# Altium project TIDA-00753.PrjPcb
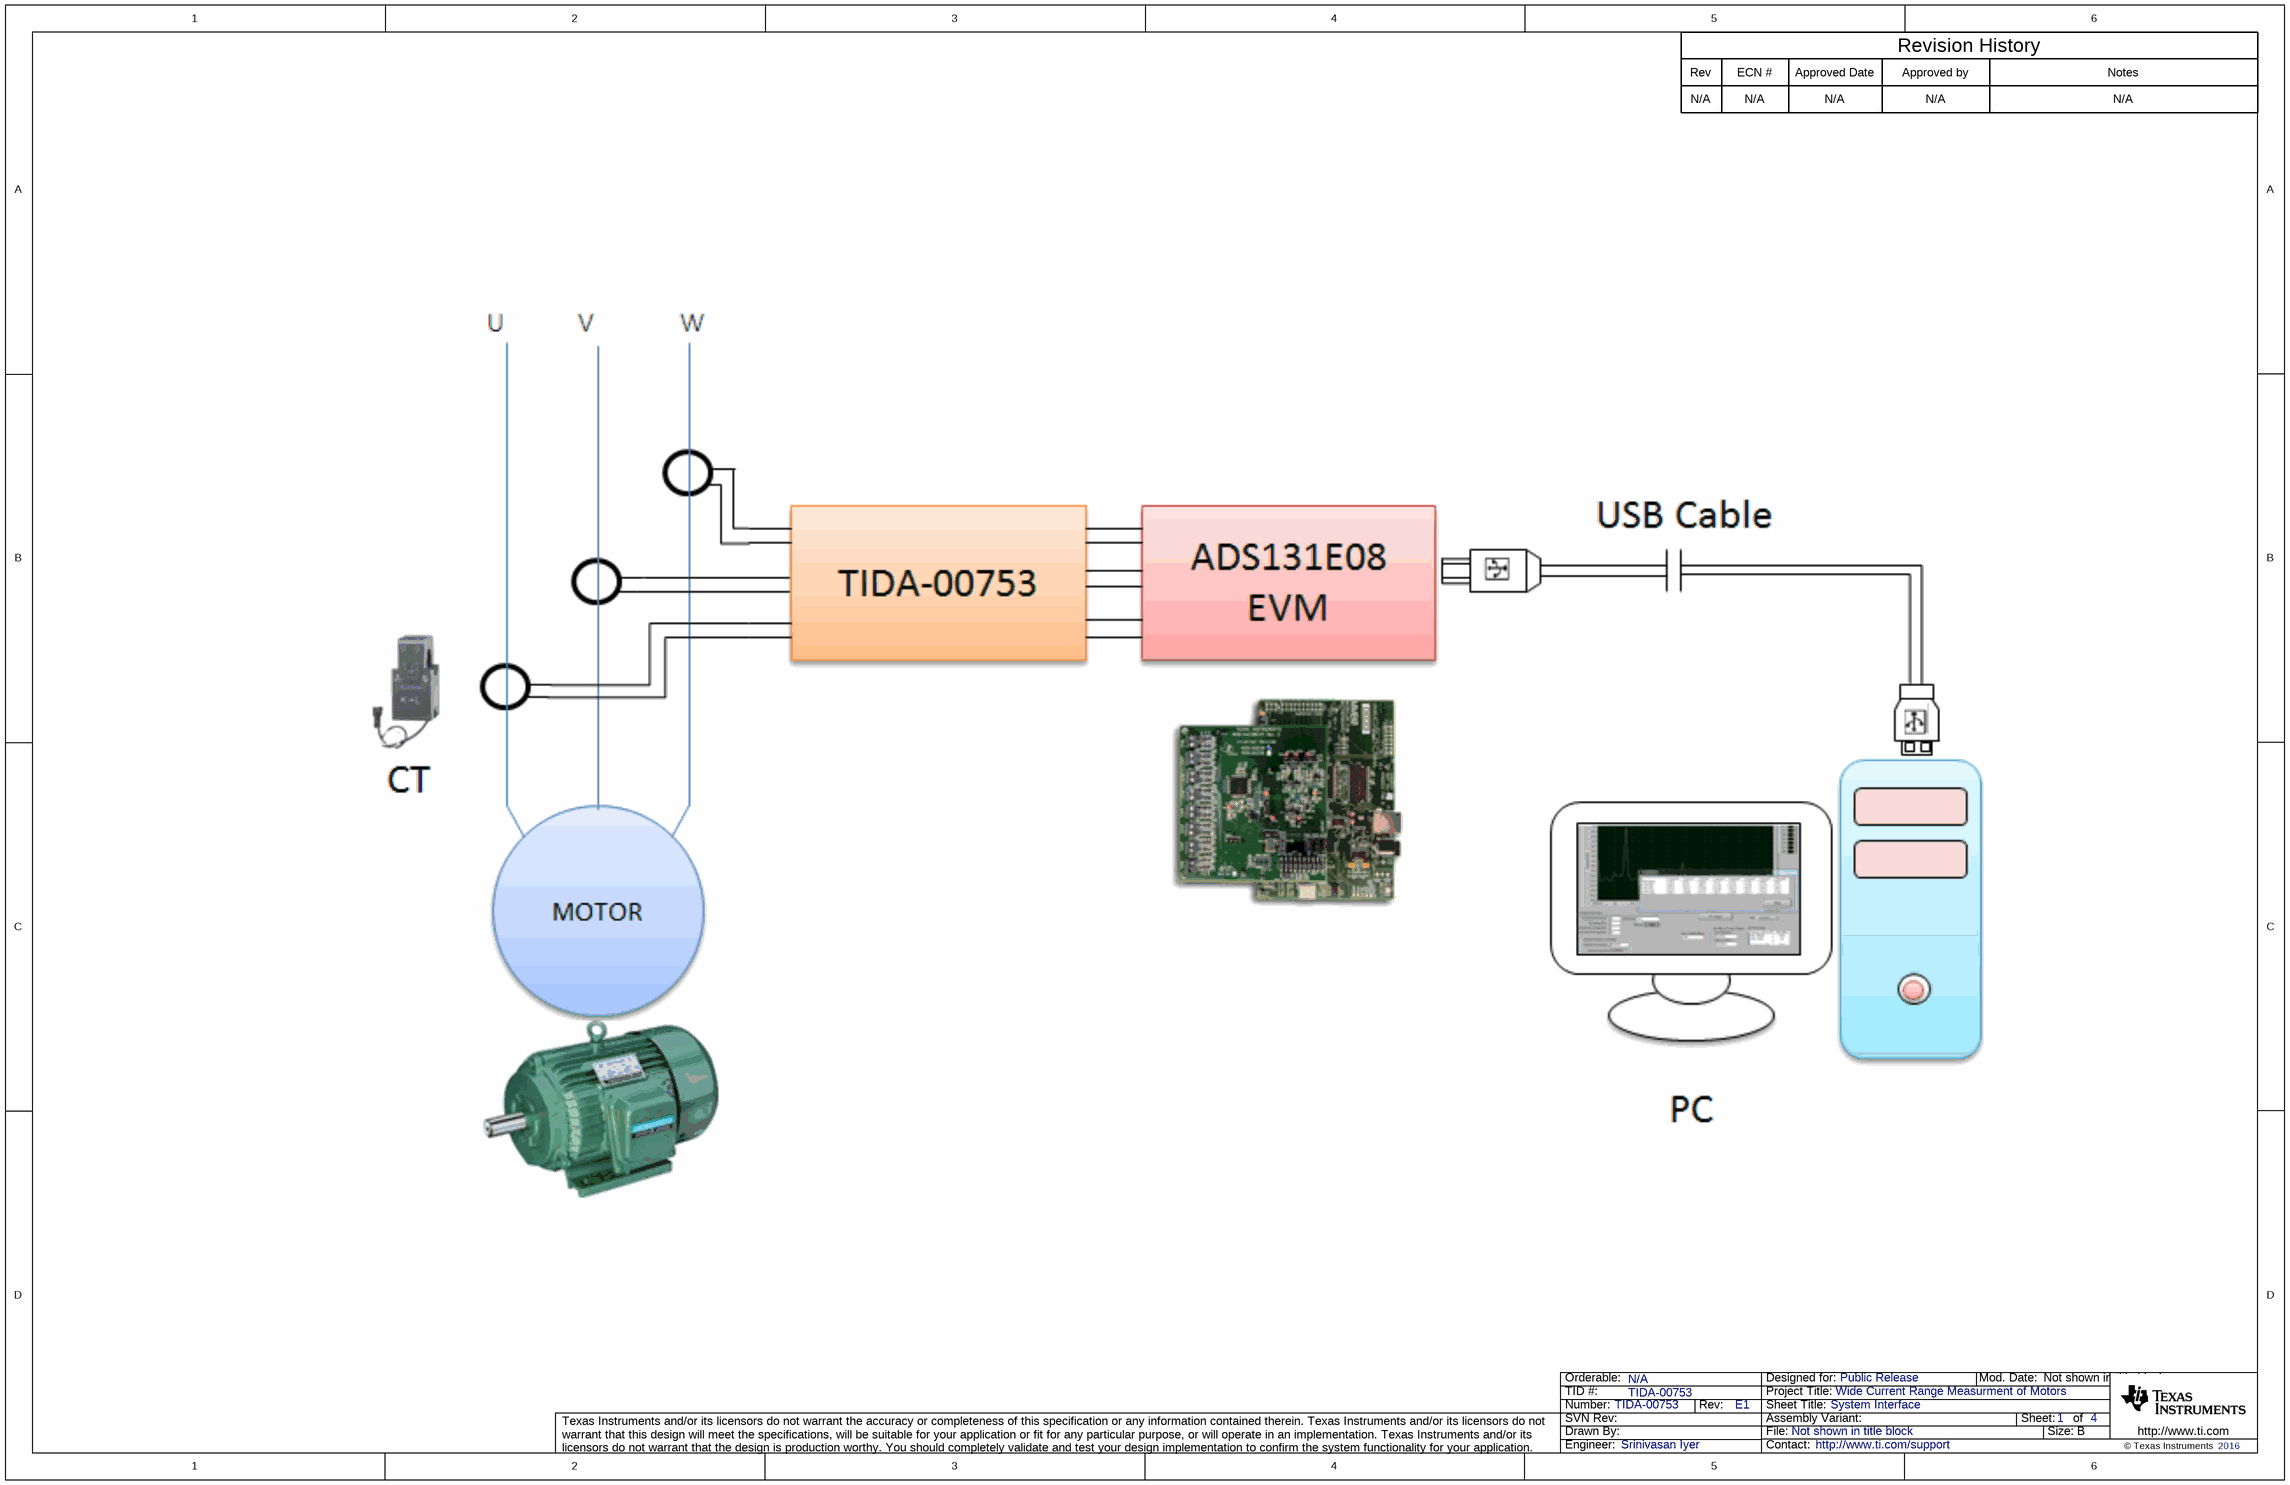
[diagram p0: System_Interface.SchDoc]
TID: TIDA-00753; TechSupport: http://www.ti.com/support; SCH_Rev: E1; PRJ_Title: Wide Current Range Measurment of Motors; PRJ_Number: TIDA-00753; PRJ_Engineer: Srinivasan Iyer; PRJ_Customer: Public Release; PCB_Rev: E1; PCB_Layout: Avinash; EVM_Orderable: N/A; CopyrightYear: 2016
4 sheets, 93 parts. Net scope: global (net labels, ports and power ports of the same name join across sheets).
Board file: TIDA-00753.PcbDoc
Sheets:
  System_Interface.SchDoc
  TIDA-00753_Block Diagram.SchDoc
  Amplifier.SchDoc
  TID_Hardware.SchDoc

## Sheet System_Interface.SchDoc: System Interface
size 431 x 279 mm; Date: Not shown in title block; ApprovedBy: Not shown in title block; CheckedBy: Not shown in title block; Author: Not shown in title block; CompanyName: Not shown in title block; Engineer: Not shown in title block; Organization: Not shown in title block; Address1: Not shown in title block; Address2: Not shown in title block; Address3: Not shown in title block; Address4: Not shown in title block; DocumentNumber: 1; Revision: Use project parameter SCH_Rev; SheetNumber: 1; SheetTotal: 4; PageSetup: Record=PageOptions¦CenterHorizontal=True¦CenterVertical=True¦PrintScale=1.00¦XCorrection=1.00¦YCorrection=1.00¦PrintKind=0¦BorderSize=5000000¦LeftOffset=0¦BottomOffset=0¦Orientation=2¦PaperLength=1000¦PaperWidth=1000¦Scale=100¦PaperSource=15¦PrintQuality=600¦MediaType=1¦DitherType=10¦PaperKind=Letter¦PrintScaleMode=1

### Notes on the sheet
- Rev
- N/A
- ECN #
- Approved Date
- Approved by
- Revision History
- Notes

## Sheet TIDA-00753_Block Diagram.SchDoc: TIDA-00753 Block Diagram
size 431 x 279 mm; Date: Not shown in title block; ApprovedBy: Not shown in title block; CheckedBy: Not shown in title block; Author: Not shown in title block; CompanyName: Not shown in title block; Engineer: Not shown in title block; Organization: Not shown in title block; Address1: Not shown in title block; Address2: Not shown in title block; Address3: Not shown in title block; Address4: Not shown in title block; DocumentNumber: 1; Revision: Use project parameter SCH_Rev; SheetNumber: 2; SheetTotal: 4; PageSetup: Record=PageOptions¦CenterHorizontal=True¦CenterVertical=True¦PrintScale=1.00¦XCorrection=1.00¦YCorrection=1.00¦PrintKind=0¦BorderSize=5000000¦LeftOffset=0¦BottomOffset=0¦Orientation=2¦PaperLength=1000¦PaperWidth=1000¦Scale=100¦PaperSource=15¦PrintQuality=600¦MediaType=1¦DitherType=10¦PaperKind=Letter¦PrintScaleMode=1
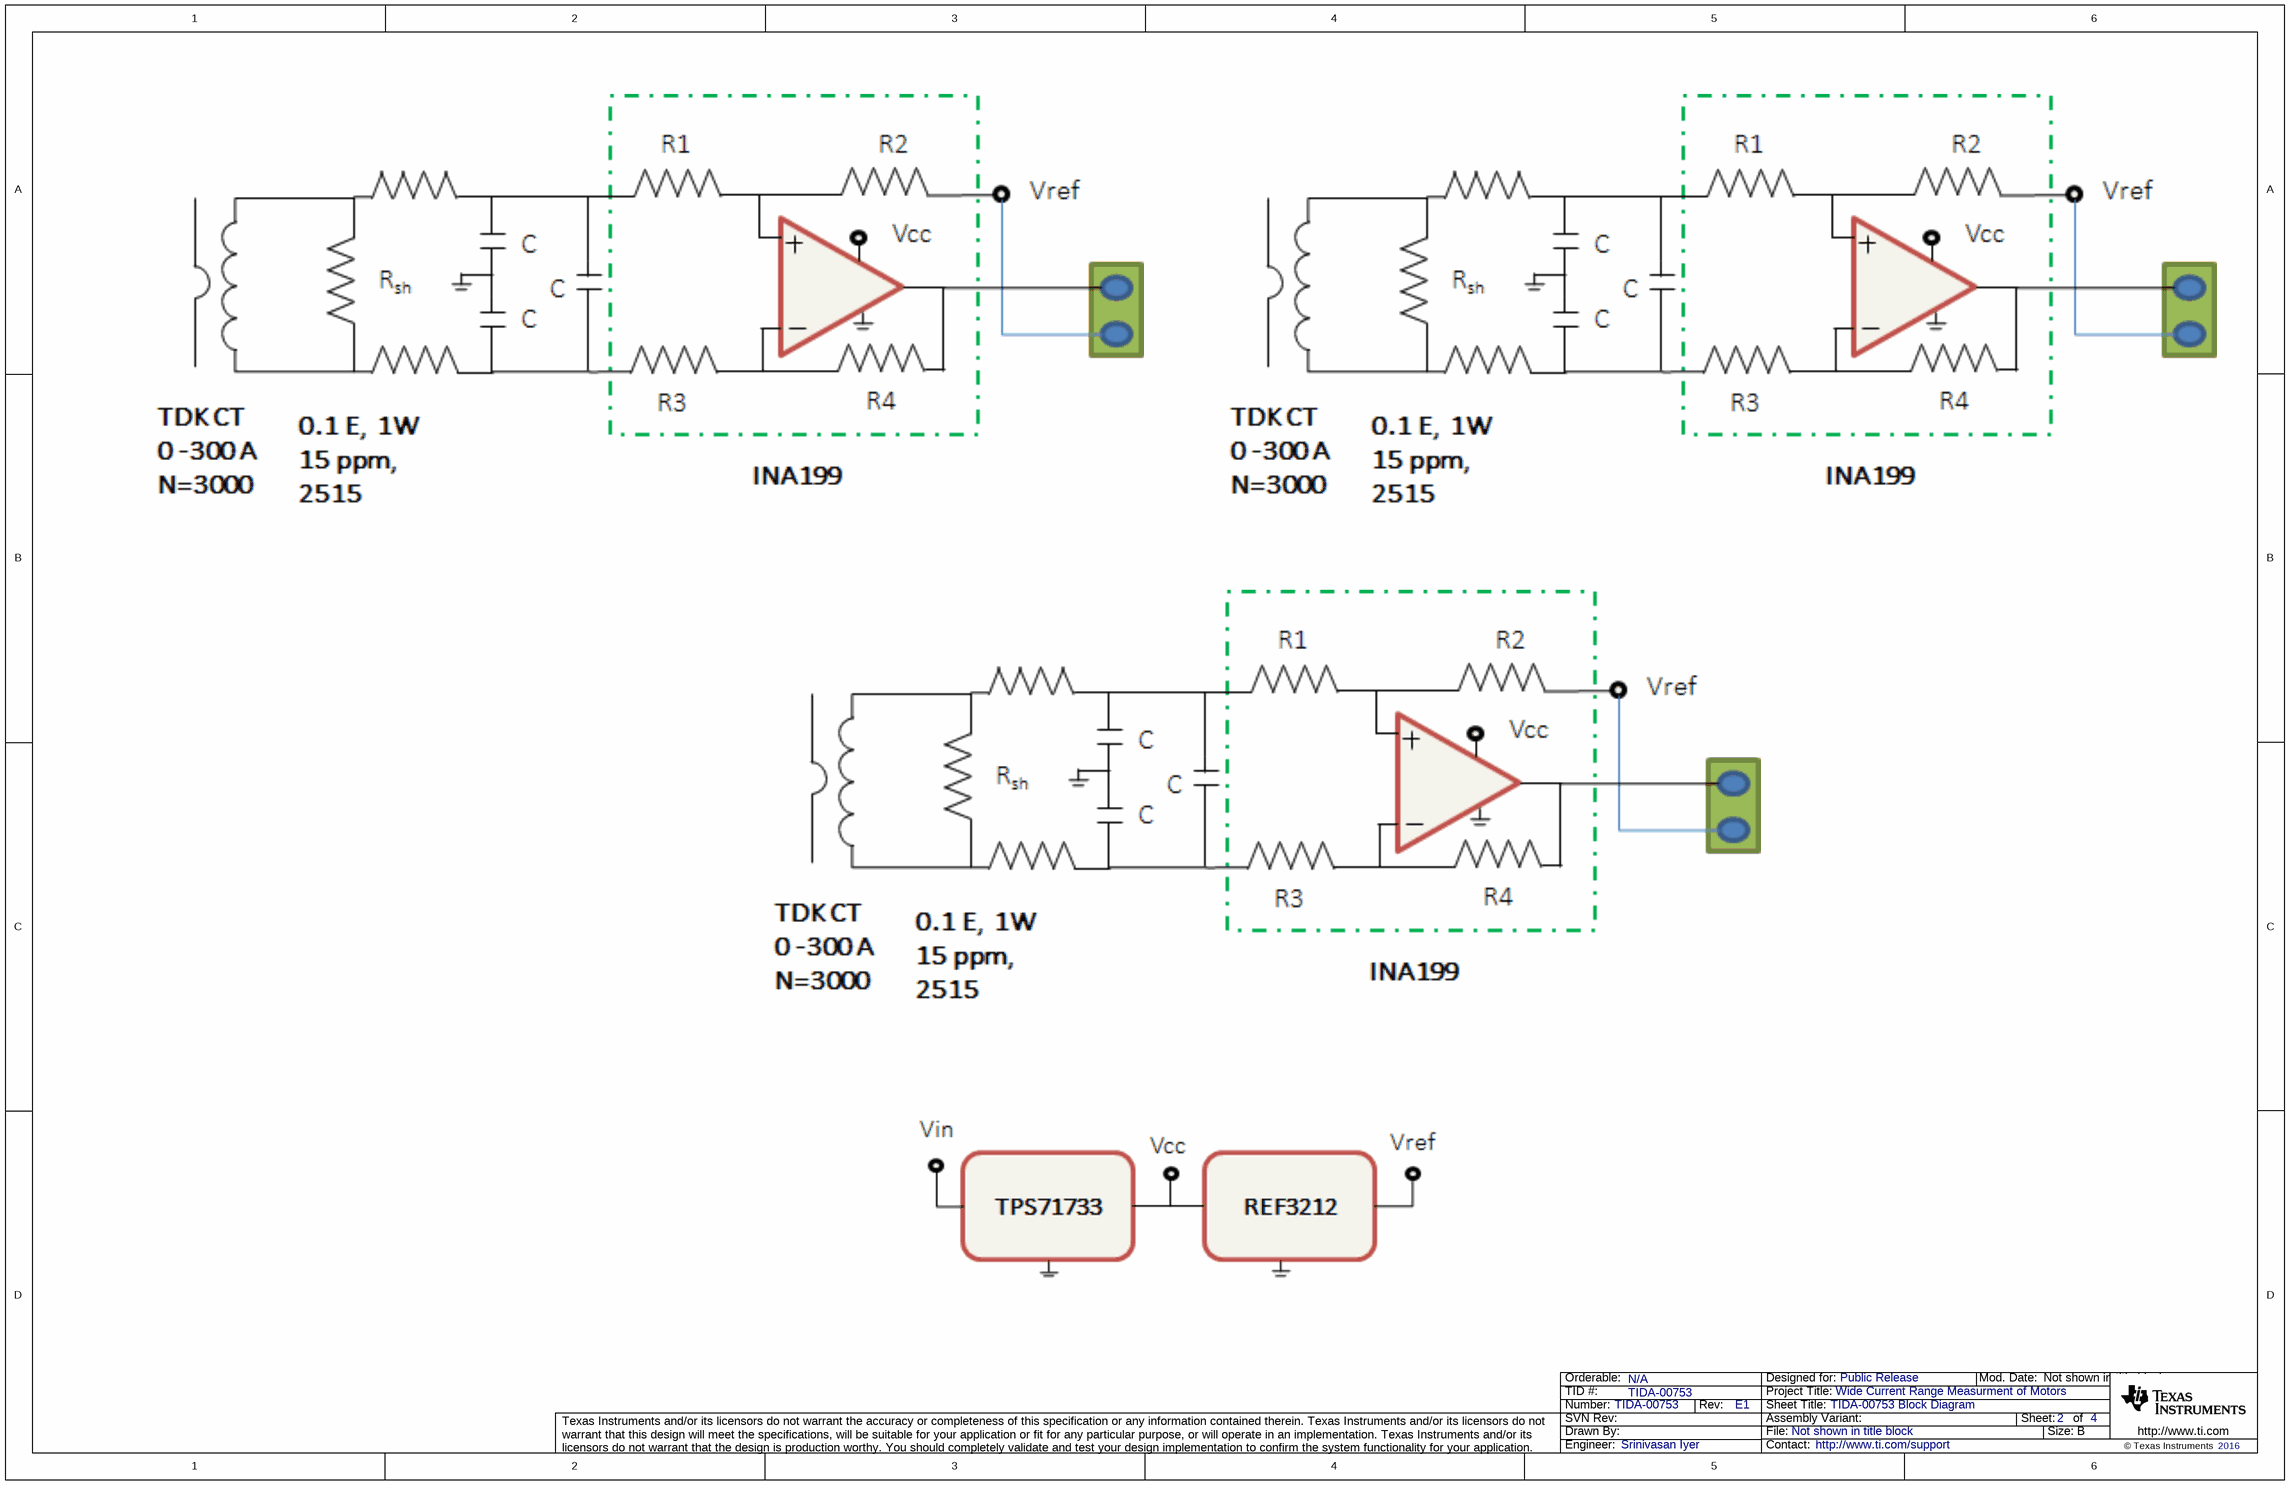
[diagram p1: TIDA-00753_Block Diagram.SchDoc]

## Sheet Amplifier.SchDoc: CT Amplifier
size 431 x 279 mm; Date: Not shown in title block; ApprovedBy: Not shown in title block; CheckedBy: Not shown in title block; Author: Not shown in title block; CompanyName: Not shown in title block; DrawnBy: Srinivasan Iyer; Engineer: Srinivasan Iyer; Organization: Not shown in title block; Address1: Not shown in title block; Address2: Not shown in title block; Address3: Not shown in title block; Address4: Not shown in title block; DocumentNumber: 1; Revision: Use project parameter SCH_Rev; SheetNumber: 3; SheetTotal: 4; PageSetup: Record=PageOptions¦CenterHorizontal=True¦CenterVertical=True¦PrintScale=0.64¦XCorrection=1.00¦YCorrection=1.00¦PrintKind=0¦BorderSize=5000000¦LeftOffset=0¦BottomOffset=0¦Orientation=2¦PaperLength=1000¦PaperWidth=1000¦Scale=100¦PaperSource=15¦PrintQuality=600¦MediaType=1¦DitherType=10¦PrintScaleMode=1¦PaperKind=Letter
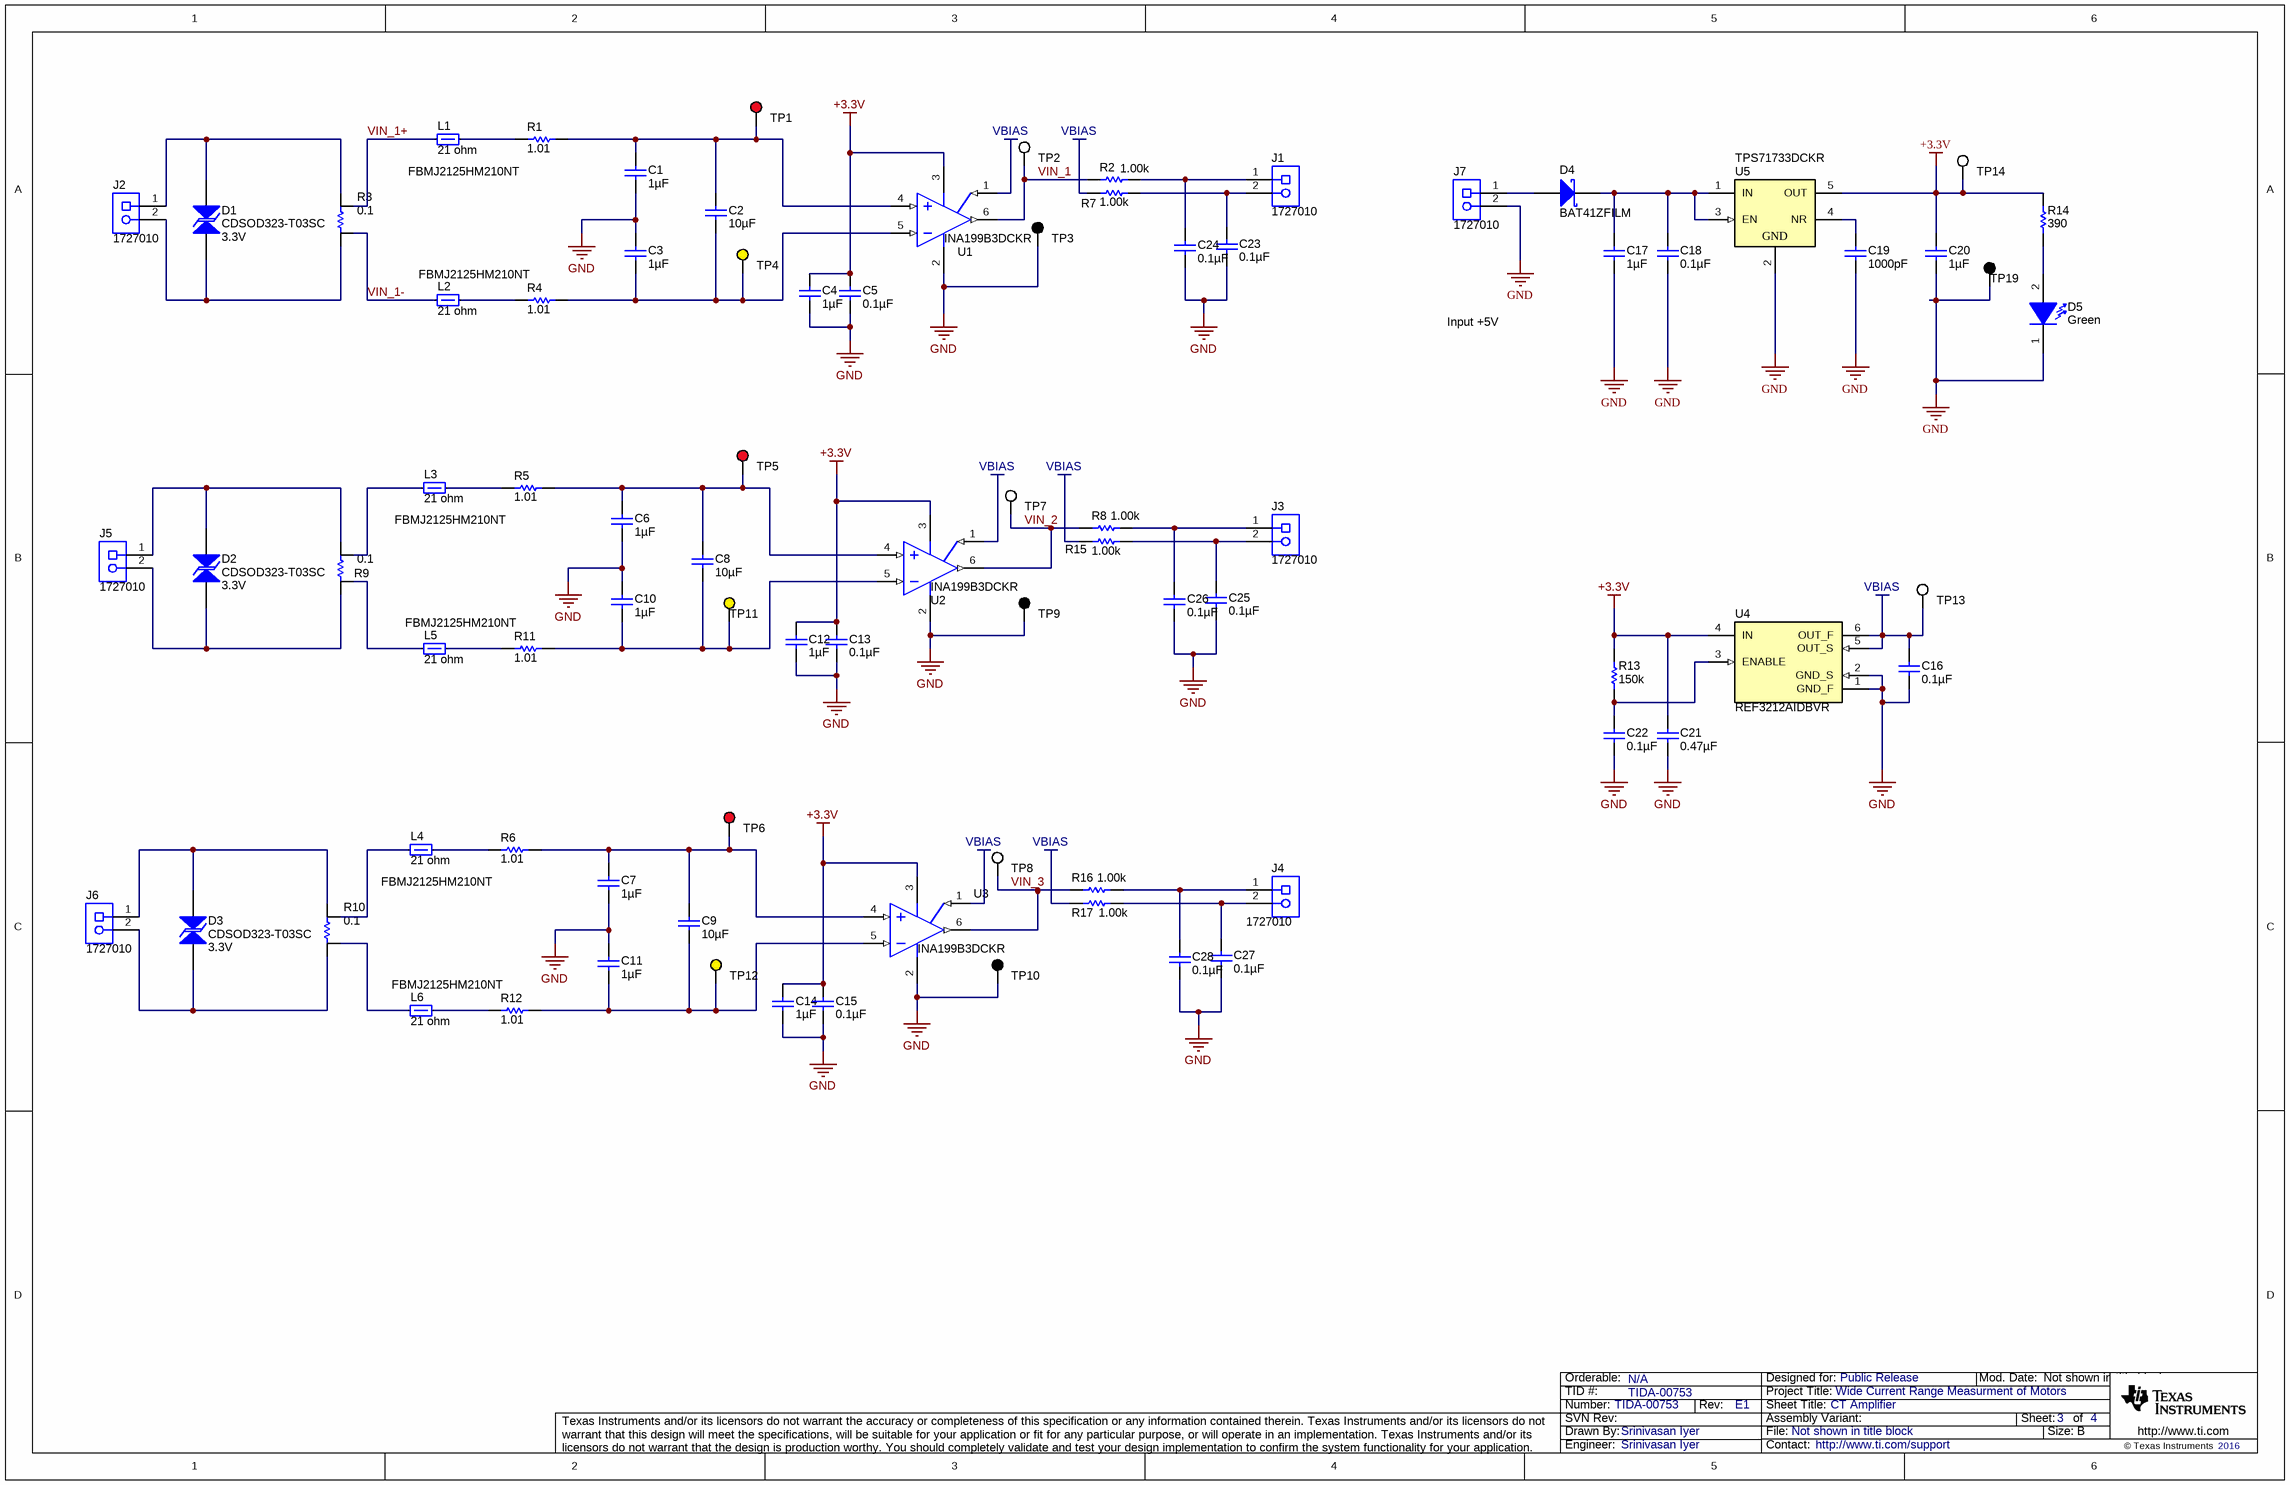
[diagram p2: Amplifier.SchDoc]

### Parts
C1  ValueDisplayed: 1µF  [0603]  (hidden comment: C1608X5R1C105K)
C2  ValueDisplayed: 10µF  [0603]  (hidden comment: GRM188R60J106ME47D)
C3  ValueDisplayed: 1µF  [0603]  (hidden comment: C1608X5R1C105K)
C4  ValueDisplayed: 1µF  [0603]  (hidden comment: C1608X5R1C105K)
C5  ValueDisplayed: 0.1µF  [0603]  (hidden comment: CGA3E2X8R1E104K080AA)
C6  ValueDisplayed: 1µF  [0603]  (hidden comment: C1608X5R1C105K)
C7  ValueDisplayed: 1µF  [0603]  (hidden comment: C1608X5R1C105K)
C8  ValueDisplayed: 10µF  [0603]  (hidden comment: GRM188R60J106ME47D)
C9  ValueDisplayed: 10µF  [0603]  (hidden comment: GRM188R60J106ME47D)
C10  ValueDisplayed: 1µF  [0603]  (hidden comment: C1608X5R1C105K)
C11  ValueDisplayed: 1µF  [0603]  (hidden comment: C1608X5R1C105K)
C12  ValueDisplayed: 1µF  [0603]  (hidden comment: C1608X5R1C105K)
C13  ValueDisplayed: 0.1µF  [0603]  (hidden comment: CGA3E2X8R1E104K080AA)
C14  ValueDisplayed: 1µF  [0603]  (hidden comment: C1608X5R1C105K)
C15  ValueDisplayed: 0.1µF  [0603]  (hidden comment: CGA3E2X8R1E104K080AA)
C16  ValueDisplayed: 0.1µF  [0603]  (hidden comment: CGA3E2X8R1E104K080AA)
C17  ValueDisplayed: 1µF  [0603]  (hidden comment: C1608X5R1C105K)
C18  ValueDisplayed: 0.1µF  [0603]  (hidden comment: CGA3E2X8R1E104K080AA)
C19  ValueDisplayed: 1000pF  [0603]  (hidden comment: C0603X102K5RACTU)
C20  ValueDisplayed: 1µF  [0603]  (hidden comment: C1608X5R1C105K)
C21  ValueDisplayed: 0.47µF  [0603]  (hidden comment: C0603C474K4RACTU)
C22  ValueDisplayed: 0.1µF  [0603]  (hidden comment: CGA3E2X8R1E104K080AA)
C23  ValueDisplayed: 0.1µF  [0603]  (hidden comment: CGA3E2X8R1E104K080AA)
C24  ValueDisplayed: 0.1µF  [0603]  (hidden comment: CGA3E2X8R1E104K080AA)
C25  ValueDisplayed: 0.1µF  [0603]  (hidden comment: CGA3E2X8R1E104K080AA)
C26  ValueDisplayed: 0.1µF  [0603]  (hidden comment: CGA3E2X8R1E104K080AA)
C27  ValueDisplayed: 0.1µF  [0603]  (hidden comment: CGA3E2X8R1E104K080AA)
C28  ValueDisplayed: 0.1µF  [0603]  (hidden comment: CGA3E2X8R1E104K080AA)
D1  CDSOD323-T03SC  value 3.3V  [SOD-323-Bi]
D2  CDSOD323-T03SC  value 3.3V  [SOD-323-Bi]
D3  CDSOD323-T03SC  value 3.3V  [SOD-323-Bi]
D4  BAT41ZFILM  [SOD-123]
D5  value Green  [WL-SMCW_GREEN]  (hidden comment: 150060GS75000)
J1  1727010  [PhoenixConact_1727010]
J2  1727010  [PhoenixConact_1727010]
J3  1727010  [PhoenixConact_1727010]
J4  1727010  [PhoenixConact_1727010]
J5  1727010  [PhoenixConact_1727010]
J6  1727010  [PhoenixConact_1727010]
J7  1727010  [PhoenixConact_1727010]
L1  value 21 ohm  [0805_HV]  (hidden comment: FBMJ2125HM210NT)
L2  value 21 ohm  [0805_HV]  (hidden comment: FBMJ2125HM210NT)
L3  value 21 ohm  [0805_HV]  (hidden comment: FBMJ2125HM210NT)
L4  value 21 ohm  [0805_HV]  (hidden comment: FBMJ2125HM210NT)
L5  value 21 ohm  [0805_HV]  (hidden comment: FBMJ2125HM210NT)
L6  value 21 ohm  [0805_HV]  (hidden comment: FBMJ2125HM210NT)
R1  ValueDisplayed: 1.01  [0603]  (hidden comment: RT0603DRE071R01L)
R2  ValueDisplayed: 1.00k  [0603]  (hidden comment: RT0603DRE071KL)
R3  ValueDisplayed: 0.1  [CSM2512_T3]  (hidden comment: Y14870R10000B9W)
R4  ValueDisplayed: 1.01  [0603]  (hidden comment: RT0603DRE071R01L)
R5  ValueDisplayed: 1.01  [0603]  (hidden comment: RT0603DRE071R01L)
R6  ValueDisplayed: 1.01  [0603]  (hidden comment: RT0603DRE071R01L)
R7  ValueDisplayed: 1.00k  [0603]  (hidden comment: RT0603DRE071KL)
R8  ValueDisplayed: 1.00k  [0603]  (hidden comment: RT0603DRE071KL)
R9  ValueDisplayed: 0.1  [CSM2512_T3]  (hidden comment: Y14870R10000B9W)
R10  ValueDisplayed: 0.1  [CSM2512_T3]  (hidden comment: Y14870R10000B9W)
R11  ValueDisplayed: 1.01  [0603]  (hidden comment: RT0603DRE071R01L)
R12  ValueDisplayed: 1.01  [0603]  (hidden comment: RT0603DRE071R01L)
R13  ValueDisplayed: 150k  [0603]  (hidden comment: CRCW0603150KFKEA)
R14  ValueDisplayed: 390  [0603]  (hidden comment: RC0603FR-07390RL)
R15  ValueDisplayed: 1.00k  [0603]  (hidden comment: RT0603DRE071KL)
R16  ValueDisplayed: 1.00k  [0603]  (hidden comment: RT0603DRE071KL)
R17  ValueDisplayed: 1.00k  [0603]  (hidden comment: RT0603DRE071KL)
TP1  5000  [Keystone5000]  (value not drawn)
TP2  5002  [Keystone5002]  (value not drawn)
TP3  5001  [Keystone5001]  (value not drawn)
TP4  5004  [Keystone5004]  (value not drawn)
TP5  5000  [Keystone5000]  (value not drawn)
TP6  5000  [Keystone5000]  (value not drawn)
TP7  5002  [Keystone5002]  (value not drawn)
TP8  5002  [Keystone5002]  (value not drawn)
TP9  5001  [Keystone5001]  (value not drawn)
TP10  5001  [Keystone5001]  (value not drawn)
TP11  5004  [Keystone5004]  (value not drawn)
TP12  5004  [Keystone5004]  (value not drawn)
TP13  5002  [Keystone5002]  (value not drawn)
TP14  5002  [Keystone5002]  (value not drawn)
TP19  5001  [Keystone5001]  (value not drawn)
U1  INA199B3DCKR  [DCK0006A_N]
U2  INA199B3DCKR  [DCK0006A_N]
U3  INA199B3DCKR  [DCK0006A_N]
U4  REF3212AIDBVR  [DBV0006A_N]
U5  TPS71733DCKR  [DCK0005A_N]

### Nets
+3.3V: C4.1 C5.1 C12.1 C13.1 C14.1 C15.1 C20.1 C21.1 R13.2 R14.2 TP14.1 U1.3(VCC) U2.3(VCC) U3.3(VCC) U4.4(IN) U5.5(OUT)
GND: C1.2 C3.1 C4.2 C5.2 C6.2 C7.2 C10.1 C11.1 C12.2 C13.2 C14.2 C15.2 C16.2 C17.2 C18.2 C19.2 C20.2 C21.2 C22.2 C23.2 C24.2 C25.2 C26.2 C27.2 C28.2 D5.1(K) J7.2 TP3.1 TP9.1 TP10.1 TP19.1 U1.2(GND) U2.2(GND) U3.2(GND) U4.1(GND_F) U4.2(GND_S) U5.2(GND)
VBIAS: C16.1 R7.1 R15.1 R17.1 TP13.1 U1.1(REF) U2.1(REF) U3.1(REF) U4.5(OUT_S) U4.6(OUT_F)
VIN_1: R2.1 TP2.1 U1.6(OUT)
VIN_1+: L1.1 R3.3
VIN_1-: L2.1 R3.4
VIN_2: R8.1 TP7.1 U2.6(OUT)
VIN_3: R16.1 TP8.1 U3.6(OUT)
NetC1_1: C1.1 C2.1 R1.2 TP1.1 U1.4(IN+)
NetC2_2: C2.2 C3.2 R4.2 TP4.1 U1.5(IN-)
NetC6_1: C6.1 C8.1 R5.2 TP5.1 U2.4(IN+)
NetC7_1: C7.1 C9.1 R6.2 TP6.1 U3.4(IN+)
NetC8_2: C8.2 C10.2 R11.2 TP11.1 U2.5(IN-)
NetC9_2: C9.2 C11.2 R12.2 TP12.1 U3.5(IN-)
NetC17_1: C17.1 C18.1 D4.1(K) U5.1(IN) U5.3(EN)
NetC19_1: C19.1 U5.4(NR)
NetC22_1: C22.1 R13.1 U4.3(ENABLE)
NetC23_1: C23.1 J1.2 R7.2
NetC24_1: C24.1 J1.1 R2.2
NetC25_1: C25.1 J3.2 R15.2
NetC26_1: C26.1 J3.1 R8.2
NetC27_1: C27.1 J4.2 R17.2
NetC28_1: C28.1 J4.1 R16.2
NetD1_1: D1.1 J2.2 R3.2
NetD1_2: D1.2 J2.1 R3.1
NetD2_1: D2.1 J5.2 R9.2
NetD2_2: D2.2 J5.1 R9.1
NetD3_1: D3.1 J6.2 R10.2
NetD3_2: D3.2 J6.1 R10.1
NetD4_2: D4.2(A) J7.1
NetD5_2: D5.2(A) R14.1
NetL1_2: L1.2 R1.1
NetL2_2: L2.2 R4.1
NetL3_1: L3.1 R9.3
NetL3_2: L3.2 R5.1
NetL4_1: L4.1 R10.3
NetL4_2: L4.2 R6.1
NetL5_1: L5.1 R9.4
NetL5_2: L5.2 R11.1
NetL6_1: L6.1 R10.4
NetL6_2: L6.2 R12.1

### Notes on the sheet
- Input +5V

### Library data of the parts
C1 C3 C4 C6 C7 C10-C12 C14 C17 C20 = C1608X5R1C105K: CAP, CERM, 1 µF, 16 V, +/- 10%, X5R, 0603; Manufacturer: TDK; Polarized: N; CompType: Capacitor; Value: 1uF; U/M: EA; Cap_F: 0.000001; Tolerance_%: 10; ESR_ohm: 0.0057; Value1: 0.0057 ohm; VDC_V: 16; Value2: 16V; TaMin_C: -55; TaMax_C: 85; AEC Category: Q200
C2 C8 C9 = GRM188R60J106ME47D: CAP, CERM, 10 µF, 6.3 V, +/- 20%, X5R, 0603; Manufacturer: MuRata; Polarized: N; CompType: Capacitor; Value: 10uF; U/M: EA; Cap_F: 0.00001; Tolerance_%: 20; ESR_ohm: 0.009; Value1: 0.009 ohm; VDC_V: 6.3; Value2: 6.3V; IRMS_A: 2.74; TaMin_C: -55; TaMax_C: 125; AEC Category: Q200
C5 C13 C15 C16 C18 C22-C28 = CGA3E2X8R1E104K080AA: CAP, CERM, 0.1 µF, 25 V, +/- 10%, X8R, AEC-Q200 Grade 0, 0603; Manufacturer: TDK; Polarized: N; CompType: Capacitor; Value: 0.1uF; U/M: EA; Cap_F: 0.0000001; Tolerance_%: 10; Value1: Unknown; VDC_V: 25; Value2: 25V; TaMin_C: -55; TaMax_C: 150; AEC Category: Q200; AEC Qualified: Y; AEC Grade: 0
C19 = C0603X102K5RACTU: CAP, CERM, 1000 pF, 50 V, +/- 10%, X7R, 0603; Manufacturer: Kemet; Polarized: N; CompType: Capacitor; Value: 1000pF; U/M: EA; Cap_F: 0.000000001; Tolerance_%: 10; Value1: Unknown; VDC_V: 50; Value2: 50V; TaMin_C: -55; TaMax_C: 125; AEC Category: Q200
C21 = C0603C474K4RACTU: CAP, CERM, 0.47 µF, 16 V, +/- 10%, X7R, 0603; Manufacturer: Kemet; Polarized: N; CompType: Capacitor; Value: 0.47uF; U/M: EA; Cap_F: 0.00000047; Tolerance_%: 10; Value1: Unknown; VDC_V: 16; Value2: 16V; TaMin_C: -55; TaMax_C: 125; AEC Category: Q200
D1-D3 = CDSOD323-T03SC: Diode, TVS, Bi, 3.3 V, 400 W, SOD323, 2-Leads, Body 1.9x1.45mm, No Polarity Mark; Manufacturer: Bourns; U/M: EA; Power_W: 400; Vr_V: 3.3; Value1: 400W; AEC Category: Q101; AEC Qualified: N
D4 = BAT41ZFILM: Diode, Schottky, 100 V, 0.2 A, SOD-123; Manufacturer: STMicroelectronics; U/M: EA; Vf_V: 1; Value: 100V; Value1: 0.2A; Value2: 1V; Io_A: 0.2; Vr_V: 100; TJmax_C: 150; AEC Category: Q101
D5 = 150060GS75000: LED, Green, SMD; Manufacturer: Wurth Elektronik; Type: InGaN; Vf_V: 3.2; Value2: 3.2V; Io_A: 0.02; Tjmax_C: 85; Value1: W; Angle: 140; U/M: EA
J1-J7 = 1727010: Conn Term Block, 2POS, 3.81mm, TH; Manufacturer: Phoenix Contact; SymbolCreator: a0412235; CompType: Terminal Block; U/M: EA; Value: 2x1
L1-L6 = FBMJ2125HM210NT: Ferrite Bead, 21 ohm @ 100 MHz, 6 A, 0805; Manufacturer: Taiyo Yuden; Imax_A: 6; DCR_ohm: 0.004; Value1: 0.004 ohm; Value2: 6A; ZTyp@100MHz_Ohm: 21
R1 R4-R6 R11 R12 = RT0603DRE071R01L: RES, 1.01, 0.5%, 0.1 W, 0603; Manufacturer: Yageo America; CompType: Resistor; Value: 1.01; Value_Code: 1R01; Tolerance_%: 0.5; Power_W: 0.1; Value2: 0.1W; VDC_V: 75; TempCo: 50 ppm/C; EIA_Code: E192; U/M: EA; AEC Category: Q200
R2 R7 R8 R15-R17 = RT0603DRE071KL: RES, 1.00 k, 0.5%, 0.1 W, 0603; Manufacturer: Yageo America; CompType: Resistor; Value: 1.00k; Res_ohm: 1000; Value_Code: 1k00; Tolerance_%: 0.5; Power_W: 0.1; Value2: 0.1W; VDC_V: 75; TempCo: 50 ppm/C; EIA_Code: E192; U/M: EA; AEC Category: Q200
R3 R9 R10 = Y14870R10000B9W: RES, 0.1, 0.1%, 1 W, 6.35x3.175mm; Manufacturer: Vishay Foil Resistors; CompType: Resistor; Value: 0.1; Value_Code: R100; Power_W: 1; Value2: 1W; TempCo: 15 ppm/C; EIA_Code: E192; U/M: EA; AEC Category: Q200; AEC Qualified: N
R13 = CRCW0603150KFKEA: RES, 150 k, 1%, 0.1 W, 0603; Manufacturer: Vishay-Dale; CompType: Resistor; Value: 150k; Res_ohm: 150000; Tolerance_%: 1; Power_W: 0.1; Value2: 0.1W; VDC_V: 75; TempCo: 100 ppm/C; EIA_Code: E96; U/M: EA; AEC Category: Q200
R14 = RC0603FR-07390RL: RES, 390, 1%, 0.1 W, 0603; Manufacturer: Yageo America; CompType: Resistor; Value: 390; Value_Code: 390R; Tolerance_%: 1; Power_W: 0.1; Value2: 0.1W; VDC_V: 150; TempCo: 200 ppm/C; U/M: EA; AEC Category: Q200
TP1 TP5 TP6 = 5000: Test Point, Miniature, Red, TH; Manufacturer: Keystone; CompType: Test Point Loop; U/M: EA
TP2 TP7 TP8 TP13 TP14 = 5002: Test Point, Miniature, White, TH; Manufacturer: Keystone; CompType: Test Point Loop; U/M: EA
TP3 TP9 TP10 TP19 = 5001: Test Point, Miniature, Black, TH; Manufacturer: Keystone; CompType: Test Point Loop; U/M: EA
TP4 TP11 TP12 = 5004: Test Point, Miniature, Yellow, TH; Manufacturer: Keystone; CompType: Test Point Loop; U/M: EA
U1-U3 = INA199A1DCKR: Voltage Output, High or Low Side Measurement, Bi-Directional Zerø-Drift Series Current-Shunt Monitor, DCK0006A; Alternate PartNumber: INA199B3DCKT; Manufacturer: Texas Instruments; SymbolCreator: a0411947; CompType: IC; U/M: EA
U4 = REF3212AIDBVR: 1.25 V, 4 ppm / degC, 100 uA Series (Bandgap) Voltage Reference, -40 to 125 degC, 6-pin SOT-23 (DBV), Green (RoHS & no Sb/Br); Manufacturer: Texas Instruments; Alternate PartNumber: Equivalent; Initial Accuracy @ 25/deg C(%): 0.2; Iout/Iz(Max)(mA): 10; Iq(Max)(uA): 120; Rating: Catalog; SubFamily: Series Voltage Reference; Temp Coeff(Max)(ppm/ degree C): 7; Temp Coeff(Typ)(ppm/ degree C): 4; VI(Max)(V): 5.5; VI(Min)(V): 1.8; VO(V): 1.25
U5 = TPS71733DCKR: Single Output High PSRR LDO, 150 mA, Fixed 3.3 V Output, 2.5 to 6.5 V Input, with Low IQ, 5-pin SC70 (DCK), -40 to 85 degC, Green (RoHS & no Sb/Br); Manufacturer: Texas Instruments; Alternate PartNumber: Equivalent; Accuracy(%): 3; Fixed Output Options(V): 3.3; Iout(Max)(A): 0.15; Iq(Typ)(mA): 0.05; SubFamily: Single Channel LDO; Vdo(Typ)(mV): 170; Vin(Max)(V): 6.5; Vin(Min)(V): 2.5

## Sheet TID_Hardware.SchDoc
size 431 x 279 mm; Date: Not shown in title block; ApprovedBy: Not shown in title block; CheckedBy: Not shown in title block; Author: Not shown in title block; CompanyName: Not shown in title block; Engineer: Not shown in title block; Organization: Not shown in title block; Address1: Not shown in title block; Address2: Not shown in title block; Address3: Not shown in title block; Address4: Not shown in title block; DocumentNumber: 1; Revision: Use project parameter SCH_Rev; SheetNumber: 4; SheetTotal: 4; PageSetup: Record=PageOptions¦CenterHorizontal=True¦CenterVertical=True¦PrintScale=1.00¦XCorrection=1.00¦YCorrection=1.00¦PrintKind=0¦BorderSize=5000000¦LeftOffset=0¦BottomOffset=0¦Orientation=2¦PaperLength=1000¦PaperWidth=1000¦Scale=100¦PaperSource=15¦PrintQuality=600¦MediaType=1¦DitherType=10¦PaperKind=Letter¦PrintScaleMode=1
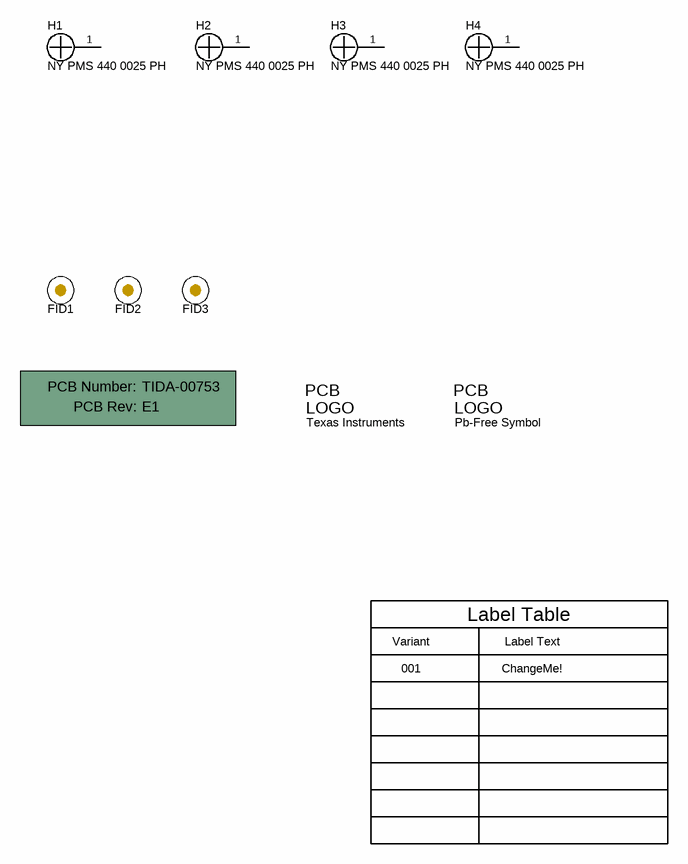
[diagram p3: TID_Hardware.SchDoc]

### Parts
FID1  Fiducial  [Fiducial10-20]  (value not drawn)
FID2  Fiducial  [Fiducial10-20]  (value not drawn)
FID3  Fiducial  [Fiducial10-20]  (value not drawn)
H1  NY PMS 440 0025 PH  [NY PMS 440 0025 PH]
H2  NY PMS 440 0025 PH  [NY PMS 440 0025 PH]
H3  NY PMS 440 0025 PH  [NY PMS 440 0025 PH]
H4  NY PMS 440 0025 PH  [NY PMS 440 0025 PH]
Logo1  Texas Instruments  [TI_Stacked_Overlay_Small]  (no BOM)
Logo2  Pb-Free Symbol  [Pb-Free_Overlay_Small]  (no BOM)
TIDA_00753  Printed Circuit Board  (value not drawn)  (mechanical)

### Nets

Not connected (* = marked no-connect by the designer): H1 1; H2 1; H3 1; H4 1

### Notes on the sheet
- Variant
- Label Table
- Label Text
- 001
- ChangeMe!

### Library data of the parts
FID1-FID3 = Fiducial: Fiducial mark.  There is nothing to buy or mount.; SymbolCreator: codlsc
H1-H4 = NY PMS 440 0025 PH: Machine Screw, Round, #4-40 x 1/4, Nylon, Philips panhead; Manufacturer: B&F Fastener Supply; CompType: Hardware; SymbolCreator: codlsc; U/M: EA
Logo1 = TI_Logo: Texas Instrument Corporate Signature; SymbolCreator: codlsc
Logo2 = Pb-Free: SymbolCreator: a0412235
TIDA_00753 = PCB: Manufacturer: Any; PartNumber: TIDA-00753; SymbolCreator: a0412235

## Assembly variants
001: not fitted C16 C23 C24 C25 C26 C27 C28 FID1 FID2 FID3 R2 R7 R8 R15 R16 R17 U1 U2 U3 U4 U5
